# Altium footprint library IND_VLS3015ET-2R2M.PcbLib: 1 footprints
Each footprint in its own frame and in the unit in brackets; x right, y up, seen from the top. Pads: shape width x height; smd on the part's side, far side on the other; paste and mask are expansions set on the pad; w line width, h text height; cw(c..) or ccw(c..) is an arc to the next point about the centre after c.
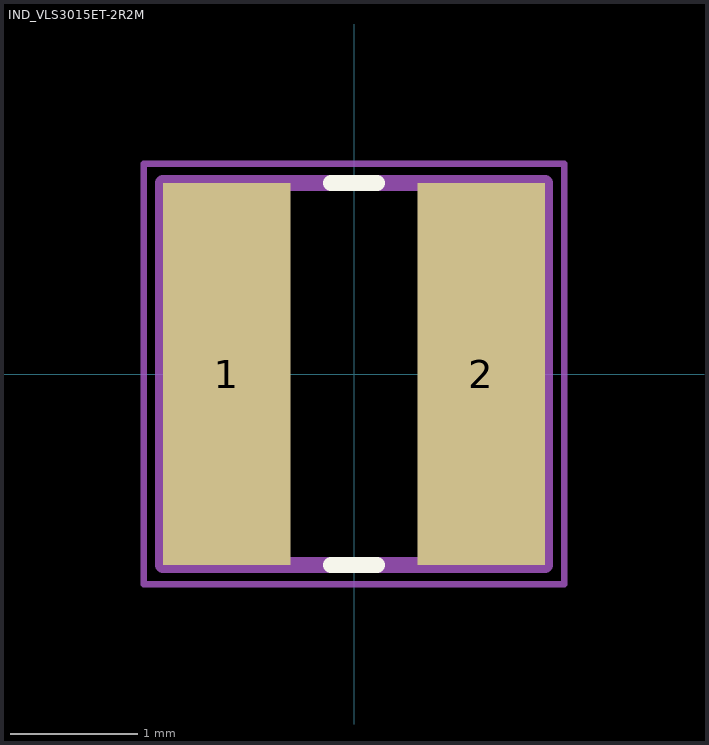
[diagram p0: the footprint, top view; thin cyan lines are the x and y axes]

## IND_VLS3015ET-2R2M [mm]
height 1.5
pads (2):
  rect 1x3 smd: 1(-1,0) 2(1,0)
Top Overlay:
  lines w0.127: -0.18,-1.5 0.18,-1.5 ; -0.18,1.5 0.18,1.5
Mechanical 13:
  lines w0.127: -1.5,-1.5 -1.5,1.5 1.5,1.5 1.5,-1.5 -1.5,-1.5
Mechanical 15:
  lines w0.05: -1.651,-1.651 -1.651,1.651 1.651,1.651 1.651,-1.651 -1.651,-1.651
3D body "step_temp.STEP": height 1.5, standoff 0, extent -1.5,-1.5 1.5,1.5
